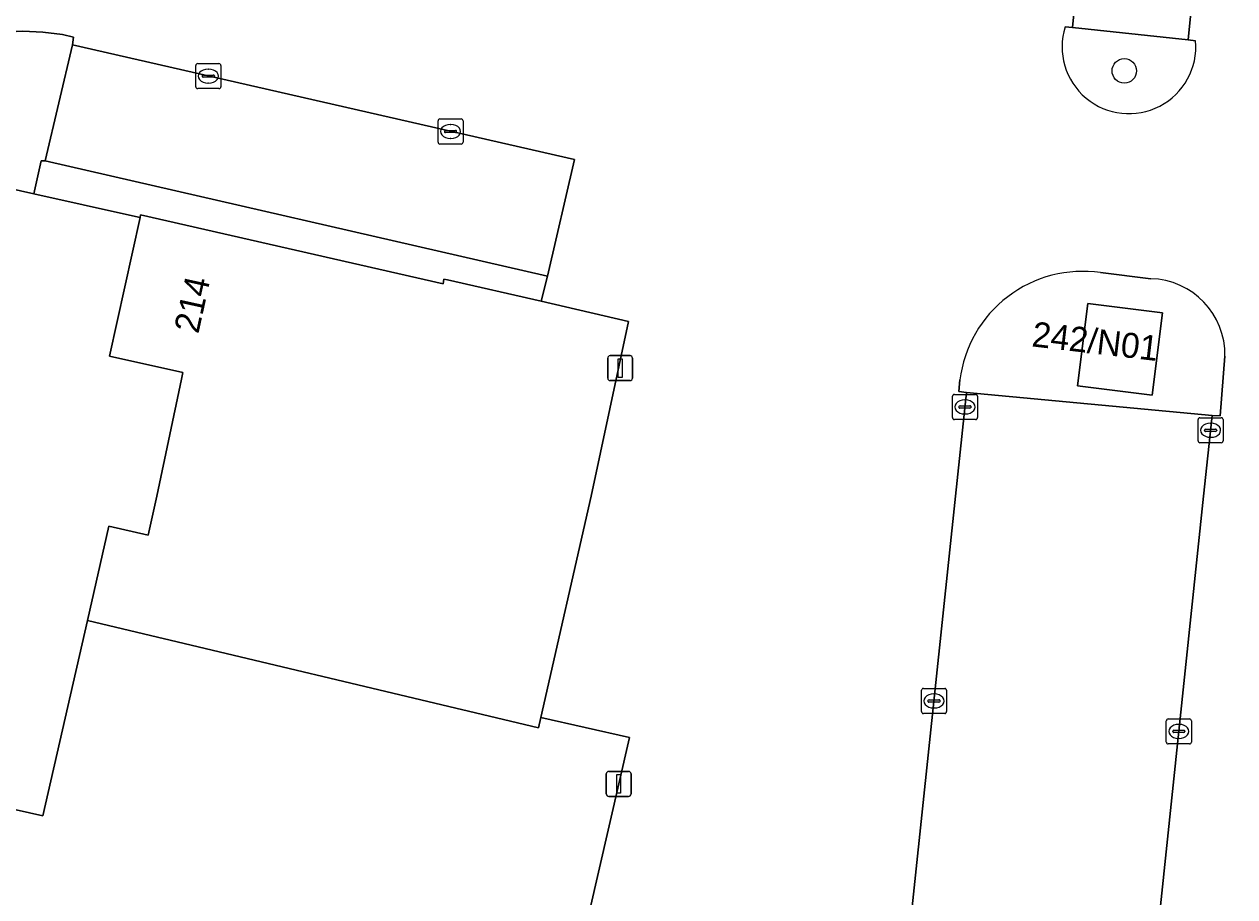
# Model space of a CAD drawing. Extents: x 161385 to 162589, y 388479 to 389756.
# Drawn here: x 162399.55 to 162447.94, y 388984 to 389018.86 of the extents above; entities that cross this region are included whole.
import ezdxf

# ---------------------------------------------------------------- set-up
doc = ezdxf.new("R2010")
doc.units = 0
for name, color, linetype in [('IMGEO_Boom', 7, 'Continuous'), ('IMGEO_Groenvoorziening', 7, 'Continuous'), ('IMGEO_Kolk', 7, 'Continuous'), ('IMGEO_Lichtmast', 7, 'Continuous'), ('IMGEO_Pand', 7, 'Continuous'), ('IMGEO_Pand_nummerreeks', 7, 'Continuous'), ('IMGEO_Parkeervlak_open', 7, 'Continuous'), ('IMGEO_Rijbaan_lokaal_open', 7, 'Continuous'), ('IMGEO_Voetpad_open', 7, 'Continuous')]:
    doc.layers.add(name, color=color, linetype=linetype)

msp = doc.modelspace()

# ---------------------------------------------------------------- linework, layer by layer
at = {"layer": 'IMGEO_Boom'}
msp.add_circle((162443.526, 389017), 0.489, dxfattribs=at)
at = {"layer": 'IMGEO_Groenvoorziening'}
for points in [[(162393.225, 389001.138), (162393.088, 389000.432), (162394.77, 389000), (162395.617, 388999.783), (162396.134, 389000), (162396.21, 389000.177), (162398.868, 389012.324), (162399.944, 389012.084), (162400.231, 389013.402), (162400.391, 389013.408), (162401.48, 389018.039), (162401.524, 389018.342), (162401.09, 389018.447), (162400.295, 389018.551), (162399.494, 389018.583), (162398.693, 389018.543), (162397.899, 389018.432), (162397.197, 389018.273)], [(162444.641, 389004.038), (162441.653, 389004.415), (162442.067, 389007.703), (162445.055, 389007.326)]]:
    msp.add_lwpolyline(points, close=True, dxfattribs=at)
for points in [[(162446.375, 389018.195), (162446.083, 389018.235), (162441.458, 389018.727), (162441.158, 389018.758)], [(162444.583, 389008.695), (162442.578, 389008.937)], [(162436.958, 389004.649), (162436.917, 389004.194), (162437.221, 389004.152), (162447.038, 389003.23), (162447.362, 389003.217), (162447.548, 389005.598)]]:
    msp.add_lwpolyline(points, dxfattribs=at)
for centre, radius, start, end in [((162443.711, 389017.963), 2.674, 162.7135, 4.9678), ((162441.863, 389004.048), 4.941, 81.675, 173.0115), ((162444.513, 389005.66), 3.036, 358.8322, 88.673)]:
    msp.add_arc(centre, radius, start, end, dxfattribs=at)
at = {"layer": 'IMGEO_Kolk'}
for p, q in [((162406.413, 389016.364), (162406.413, 389017.216)), ((162406.488, 389017.29), (162407.34, 389017.29)), ((162407.414, 389017.216), (162407.414, 389016.364)), ((162406.672, 389016.784), (162406.672, 389016.796)), ((162407.11, 389016.747), (162406.712, 389016.747)), ((162406.715, 389016.833), (162407.113, 389016.833)), ((162406.901, 389017.07), (162406.926, 389017.07)), ((162407.156, 389016.796), (162407.156, 389016.784)), ((162407.34, 389016.29), (162406.488, 389016.29)), ((162406.924, 389016.51), (162406.899, 389016.51)), ((162416.097, 389014.151), (162416.097, 389015.003)), ((162416.172, 389015.077), (162417.024, 389015.077)), ((162416.585, 389014.857), (162416.61, 389014.857)), ((162417.098, 389015.003), (162417.098, 389014.151)), ((162416.356, 389014.571), (162416.356, 389014.583)), ((162416.794, 389014.534), (162416.396, 389014.534)), ((162416.399, 389014.62), (162416.797, 389014.62)), ((162416.608, 389014.297), (162416.583, 389014.297)), ((162416.84, 389014.583), (162416.84, 389014.571)), ((162417.024, 389014.077), (162416.172, 389014.077)), ((162436.733, 389004.07), (162437.585, 389004.07)), ((162436.658, 389003.144), (162436.658, 389003.996)), ((162436.917, 389003.564), (162436.917, 389003.576)), ((162436.96, 389003.613), (162437.358, 389003.613)), ((162437.146, 389003.85), (162437.171, 389003.85)), ((162437.401, 389003.576), (162437.401, 389003.564)), ((162437.659, 389003.996), (162437.659, 389003.144)), ((162437.355, 389003.527), (162436.957, 389003.527)), ((162437.169, 389003.29), (162437.144, 389003.29)), ((162446.551, 389003.138), (162447.403, 389003.138)), ((162437.585, 389003.07), (162436.733, 389003.07)), ((162446.476, 389002.212), (162446.476, 389003.064)), ((162446.735, 389002.632), (162446.735, 389002.644)), ((162446.778, 389002.681), (162447.176, 389002.681)), ((162446.964, 389002.918), (162446.989, 389002.918)), ((162447.219, 389002.644), (162447.219, 389002.632)), ((162447.477, 389003.064), (162447.477, 389002.212)), ((162447.403, 389002.138), (162446.551, 389002.138)), ((162447.173, 389002.595), (162446.775, 389002.595)), ((162446.987, 389002.358), (162446.962, 389002.358)), ((162435.42, 388991.396), (162435.42, 388992.248)), ((162435.495, 388992.322), (162436.347, 388992.322)), ((162435.908, 388992.102), (162435.933, 388992.102)), ((162436.421, 388992.248), (162436.421, 388991.396)), ((162435.679, 388991.816), (162435.679, 388991.828)), ((162436.117, 388991.779), (162435.719, 388991.779)), ((162435.722, 388991.865), (162436.12, 388991.865)), ((162435.931, 388991.542), (162435.906, 388991.542)), ((162436.163, 388991.828), (162436.163, 388991.816)), ((162436.347, 388991.322), (162435.495, 388991.322)), ((162445.206, 388990.181), (162445.206, 388991.033)), ((162445.281, 388991.107), (162446.133, 388991.107)), ((162446.207, 388991.033), (162446.207, 388990.181)), ((162445.465, 388990.601), (162445.465, 388990.613)), ((162445.903, 388990.564), (162445.505, 388990.564)), ((162445.508, 388990.65), (162445.906, 388990.65)), ((162445.694, 388990.887), (162445.719, 388990.887)), ((162445.949, 388990.613), (162445.949, 388990.601)), ((162446.133, 388990.107), (162445.281, 388990.107)), ((162445.717, 388990.327), (162445.692, 388990.327))]:
    msp.add_line(p, q, dxfattribs=at)
for points in [[(162406.413, 389016.364), (162406.413, 389017.216)], [(162406.488, 389017.29), (162407.34, 389017.29)], [(162407.414, 389017.216), (162407.414, 389016.364)], [(162407.34, 389016.29), (162406.488, 389016.29)], [(162416.097, 389014.151), (162416.097, 389015.003)], [(162416.172, 389015.077), (162417.024, 389015.077)], [(162417.098, 389015.003), (162417.098, 389014.151)], [(162417.024, 389014.077), (162416.172, 389014.077)], [(162436.733, 389004.07), (162437.585, 389004.07)], [(162436.658, 389003.144), (162436.658, 389003.996)], [(162437.659, 389003.996), (162437.659, 389003.144)], [(162446.551, 389003.138), (162447.403, 389003.138)], [(162437.585, 389003.07), (162436.733, 389003.07)], [(162446.476, 389002.212), (162446.476, 389003.064)], [(162447.477, 389003.064), (162447.477, 389002.212)], [(162447.403, 389002.138), (162446.551, 389002.138)], [(162435.42, 388991.396), (162435.42, 388992.248)], [(162435.495, 388992.322), (162436.347, 388992.322)], [(162436.421, 388992.248), (162436.421, 388991.396)], [(162436.347, 388991.322), (162435.495, 388991.322)], [(162445.206, 388990.181), (162445.206, 388991.033)], [(162445.281, 388991.107), (162446.133, 388991.107)], [(162446.207, 388991.033), (162446.207, 388990.181)], [(162446.133, 388990.107), (162445.281, 388990.107)]]:
    msp.add_lwpolyline(points, dxfattribs=at)
for centre, radius, start, end in [((162406.49, 389017.214), 0.0765, 91.552, 178.448), ((162406.49, 389017.214), 0.0765, 91.552, 178.448), ((162407.338, 389017.214), 0.0765, 1.552, 88.448), ((162407.338, 389017.214), 0.0765, 1.552, 88.448), ((162406.712, 389016.793), 0.0403, 85.8775, 175.7526), ((162406.709, 389016.783), 0.0366, 178.938, 274.7102), ((162407.113, 389016.79), 0.043, 264.8664, 352.4533), ((162407.117, 389016.795), 0.0386, 1.7309, 96.639), ((162406.49, 389016.366), 0.0765, 181.552, 268.448), ((162406.49, 389016.366), 0.0765, 181.552, 268.448), ((162407.338, 389016.366), 0.0765, 271.552, 358.448), ((162407.338, 389016.366), 0.0765, 271.552, 358.448), ((162416.174, 389015.001), 0.0765, 91.552, 178.448), ((162416.174, 389015.001), 0.0765, 91.552, 178.448), ((162417.022, 389015.001), 0.0765, 1.552, 88.448), ((162417.022, 389015.001), 0.0765, 1.552, 88.448), ((162416.396, 389014.58), 0.0403, 85.8775, 175.7526), ((162416.393, 389014.57), 0.0366, 178.938, 274.7102), ((162416.797, 389014.577), 0.043, 264.8664, 352.4533), ((162416.801, 389014.582), 0.0386, 1.7309, 96.639), ((162416.174, 389014.153), 0.0765, 181.552, 268.448), ((162416.174, 389014.153), 0.0765, 181.552, 268.448), ((162417.022, 389014.153), 0.0765, 271.552, 358.448), ((162417.022, 389014.153), 0.0765, 271.552, 358.448), ((162436.735, 389003.994), 0.0765, 91.552, 178.448), ((162436.735, 389003.994), 0.0765, 91.552, 178.448), ((162437.583, 389003.994), 0.0765, 1.552, 88.448), ((162437.583, 389003.994), 0.0765, 1.552, 88.448), ((162436.957, 389003.573), 0.0403, 85.8775, 175.7526), ((162437.362, 389003.575), 0.0386, 1.7309, 96.639), ((162436.735, 389003.146), 0.0765, 181.552, 268.448), ((162436.735, 389003.146), 0.0765, 181.552, 268.448), ((162436.954, 389003.563), 0.0366, 178.938, 274.7102), ((162437.358, 389003.57), 0.043, 264.8664, 352.4533), ((162437.583, 389003.146), 0.0765, 271.552, 358.448), ((162437.583, 389003.146), 0.0765, 271.552, 358.448), ((162446.553, 389003.062), 0.0765, 91.552, 178.448), ((162446.553, 389003.062), 0.0765, 91.552, 178.448), ((162447.401, 389003.062), 0.0765, 1.552, 88.448), ((162447.401, 389003.062), 0.0765, 1.552, 88.448), ((162446.775, 389002.641), 0.0403, 85.8775, 175.7526), ((162446.772, 389002.631), 0.0366, 178.938, 274.7102), ((162447.176, 389002.638), 0.043, 264.8664, 352.4533), ((162447.18, 389002.643), 0.0386, 1.7309, 96.639), ((162446.553, 389002.214), 0.0765, 181.552, 268.448), ((162446.553, 389002.214), 0.0765, 181.552, 268.448), ((162447.401, 389002.214), 0.0765, 271.552, 358.448), ((162447.401, 389002.214), 0.0765, 271.552, 358.448), ((162435.497, 388992.246), 0.0765, 91.552, 178.448), ((162435.497, 388992.246), 0.0765, 91.552, 178.448), ((162436.345, 388992.246), 0.0765, 1.552, 88.448), ((162436.345, 388992.246), 0.0765, 1.552, 88.448), ((162435.719, 388991.825), 0.0403, 85.8775, 175.7526), ((162435.716, 388991.815), 0.0366, 178.938, 274.7102), ((162436.12, 388991.822), 0.043, 264.8664, 352.4533), ((162436.124, 388991.827), 0.0386, 1.7309, 96.639), ((162435.497, 388991.398), 0.0765, 181.552, 268.448), ((162435.497, 388991.398), 0.0765, 181.552, 268.448), ((162436.345, 388991.398), 0.0765, 271.552, 358.448), ((162436.345, 388991.398), 0.0765, 271.552, 358.448), ((162445.283, 388991.031), 0.0765, 91.552, 178.448), ((162445.283, 388991.031), 0.0765, 91.552, 178.448), ((162446.131, 388991.031), 0.0765, 1.552, 88.448), ((162446.131, 388991.031), 0.0765, 1.552, 88.448), ((162445.505, 388990.61), 0.0403, 85.8775, 175.7526), ((162445.502, 388990.6), 0.0366, 178.938, 274.7102), ((162445.906, 388990.607), 0.043, 264.8664, 352.4533), ((162445.91, 388990.612), 0.0386, 1.7309, 96.639), ((162445.283, 388990.183), 0.0765, 181.552, 268.448), ((162445.283, 388990.183), 0.0765, 181.552, 268.448), ((162446.131, 388990.183), 0.0765, 271.552, 358.448), ((162446.131, 388990.183), 0.0765, 271.552, 358.448)]:
    msp.add_arc(centre, radius, start, end, dxfattribs=at)
for centre, major_axis, ratio, start_param, end_param in [((162406.9, 389016.79), (-0.387, 0.002), 0.722429, 4.712389, 7.853982), ((162406.925, 389016.79), (-0.39, 0.002), 0.717154, 1.570796, 4.712389), ((162416.584, 389014.577), (-0.387, 0.002), 0.722429, 4.712389, 7.853982), ((162416.609, 389014.577), (-0.39, 0.002), 0.717154, 1.570796, 4.712389), ((162437.145, 389003.57), (-0.387, 0.002), 0.722429, 4.712389, 7.853982), ((162437.17, 389003.57), (-0.39, 0.002), 0.717154, 1.570796, 4.712389), ((162446.963, 389002.638), (-0.387, 0.002), 0.722429, 4.712389, 7.853982), ((162446.988, 389002.638), (-0.39, 0.002), 0.717154, 1.570796, 4.712389), ((162435.907, 388991.822), (-0.387, 0.002), 0.722429, 4.712389, 7.853982), ((162435.932, 388991.822), (-0.39, 0.002), 0.717154, 1.570796, 4.712389), ((162445.693, 388990.607), (-0.387, 0.002), 0.722429, 4.712389, 7.853982), ((162445.718, 388990.607), (-0.39, 0.002), 0.717154, 1.570796, 4.712389)]:
    msp.add_ellipse(centre, major_axis=major_axis, ratio=ratio, start_param=start_param, end_param=end_param, dxfattribs=at)
at = {"layer": 'IMGEO_Lichtmast'}
for p, q in [((162422.879, 389004.722), (162422.879, 389005.522)), ((162422.879, 389005.522), (162422.879, 389004.722)), ((162422.979, 389005.622), (162423.769, 389005.622)), ((162423.769, 389005.622), (162422.979, 389005.622)), ((162423.869, 389005.522), (162423.869, 389004.722)), ((162423.869, 389004.722), (162423.869, 389005.522)), ((162423.769, 389004.622), (162422.979, 389004.622)), ((162422.979, 389004.622), (162423.769, 389004.622)), ((162422.821, 388988.108), (162422.821, 388988.908)), ((162422.821, 388988.908), (162422.821, 388988.108)), ((162422.921, 388989.008), (162423.711, 388989.008)), ((162423.711, 388989.008), (162422.921, 388989.008)), ((162423.811, 388988.908), (162423.811, 388988.108)), ((162423.811, 388988.108), (162423.811, 388988.908)), ((162423.711, 388988.008), (162422.921, 388988.008)), ((162422.921, 388988.008), (162423.711, 388988.008))]:
    msp.add_line(p, q, dxfattribs=at)
for points in [[(162423.299, 389005.497), (162423.449, 389005.497), (162423.449, 389004.747), (162423.299, 389004.747), (162423.299, 389005.497)], [(162423.241, 388988.883), (162423.391, 388988.883), (162423.391, 388988.133), (162423.241, 388988.133), (162423.241, 388988.883)]]:
    msp.add_lwpolyline(points, dxfattribs=at)
for centre, start, end in [((162422.979, 389005.522), 90, 180), ((162422.979, 389005.522), 90, 180), ((162423.769, 389005.522), 0, 90), ((162423.769, 389005.522), 360, 90), ((162422.979, 389004.722), 180, 270), ((162422.979, 389004.722), 180, 270), ((162423.769, 389004.722), 270, 0), ((162423.769, 389004.722), 270, 0), ((162422.921, 388988.908), 90, 180), ((162422.921, 388988.908), 90, 180), ((162423.711, 388988.908), 0, 90), ((162423.711, 388988.908), 360, 90), ((162422.921, 388988.108), 180, 270), ((162422.921, 388988.108), 180, 270), ((162423.711, 388988.108), 270, 0), ((162423.711, 388988.108), 270, 0)]:
    msp.add_arc(centre, 0.1, start, end, dxfattribs=at)
at = {"layer": 'IMGEO_Pand'}
for points in [[(162420.208, 388991.162), (162422.212, 389000), (162423.709, 389006.989), (162420.214, 389007.794), (162416.473, 389008.648), (162416.327, 389008.678), (162416.297, 389008.491), (162404.209, 389011.252), (162404.184, 389011.139), (162402.965, 389005.606), (162405.89, 389004.949), (162405.839, 389004.682), (162404.862, 389000), (162404.511, 388998.443), (162402.942, 388998.804), (162402.081, 388995.033), (162420.115, 388990.752)], [(162444.641, 389004.038), (162445.055, 389007.326), (162442.067, 389007.703), (162441.653, 389004.415)], [(162391.651, 388980.499), (162420.013, 388974.152), (162420.107, 388974.561), (162423.742, 388990.359), (162420.208, 388991.162), (162420.115, 388990.752), (162402.081, 388995.033), (162400.299, 388987.229), (162395.008, 388988.423), (162393.661, 388982.525), (162392.188, 388982.852)]]:
    msp.add_lwpolyline(points, close=True, dxfattribs=at)
at = {"layer": 'IMGEO_Parkeervlak_open'}
for points in [[(162446.083, 389018.235), (162449.546, 389053.274), (162444.913, 389053.751), (162441.458, 389018.727)], [(162421.544, 389013.452), (162401.48, 389018.039), (162400.391, 389013.408), (162420.472, 389008.793)], [(162447.038, 389003.23), (162437.221, 389004.152), (162436.782, 389000), (162431.67, 388951.665), (162441.51, 388950.644), (162446.698, 389000)]]:
    msp.add_lwpolyline(points, close=True, dxfattribs=at)
msp.add_lwpolyline([(162394.839, 388993.615), (162393.691, 388988.715), (162395.008, 388988.423), (162400.299, 388987.229), (162402.081, 388995.033), (162402.942, 388998.804), (162404.511, 388998.443), (162404.862, 389000), (162405.839, 389004.682), (162405.89, 389004.949), (162402.965, 389005.606), (162404.184, 389011.139), (162403.885, 389011.206), (162399.944, 389012.084), (162398.868, 389012.324), (162396.21, 389000.177), (162396.134, 389000), (162395.617, 388999.783), (162394.77, 389000), (162393.088, 389000.432), (162392.988, 389000), (162391.788, 388994.793), (162394.446, 388994.222)], dxfattribs=at)
at = {"layer": 'IMGEO_Rijbaan_lokaal_open'}
for points in [[(162441.158, 389018.758), (162441.458, 389018.727), (162444.913, 389053.751), (162444.64, 389053.772)], [(162449.834, 389053.256), (162449.546, 389053.274), (162446.083, 389018.235), (162446.375, 389018.195)], [(162399.165, 389026.921), (162397.197, 389018.273), (162397.899, 389018.432), (162398.693, 389018.543), (162399.494, 389018.583), (162400.295, 389018.551), (162401.09, 389018.447), (162401.524, 389018.342), (162401.48, 389018.039), (162421.544, 389013.452), (162420.472, 389008.793), (162420.214, 389007.794), (162423.709, 389006.989), (162422.212, 389000), (162420.208, 388991.162), (162423.742, 388990.359), (162420.107, 388974.561), (162423.624, 388973.76), (162419.993, 388957.957), (162423.507, 388957.168), (162419.878, 388941.387)], [(162442.578, 389008.937), (162444.583, 389008.695)], [(162447.548, 389005.598), (162447.362, 389003.217), (162447.038, 389003.23), (162446.698, 389000), (162441.51, 388950.644), (162441.747, 388950.626)], [(162431.396, 388951.714), (162431.67, 388951.665), (162436.782, 389000), (162437.221, 389004.152), (162436.917, 389004.194), (162436.958, 389004.649)]]:
    msp.add_lwpolyline(points, dxfattribs=at)
for centre, radius, start, end in [((162443.711, 389017.963), 2.674, 162.7135, 4.9678), ((162441.863, 389004.048), 4.941, 81.675, 173.0115), ((162444.513, 389005.66), 3.036, 358.8322, 88.673)]:
    msp.add_arc(centre, radius, start, end, dxfattribs=at)
at = {"layer": 'IMGEO_Voetpad_open'}
msp.add_lwpolyline([(162420.472, 389008.793), (162400.391, 389013.408), (162400.231, 389013.402), (162399.944, 389012.084), (162403.885, 389011.206), (162404.184, 389011.139), (162404.209, 389011.252), (162416.297, 389008.491), (162416.327, 389008.678), (162416.473, 389008.648), (162420.214, 389007.794)], close=True, dxfattribs=at)

# ---------------------------------------------------------------- texts
at = {"layer": 'IMGEO_Pand_nummerreeks'}
for s, rotation, p in [('214', 77.5744, (162406.513, 389006.466)), ('242/N01', 353.3107, (162439.8, 389005.994))]:
    msp.add_text(s, height=1, rotation=rotation, dxfattribs=at).set_placement(p)

doc.saveas('drawing.dxf')
